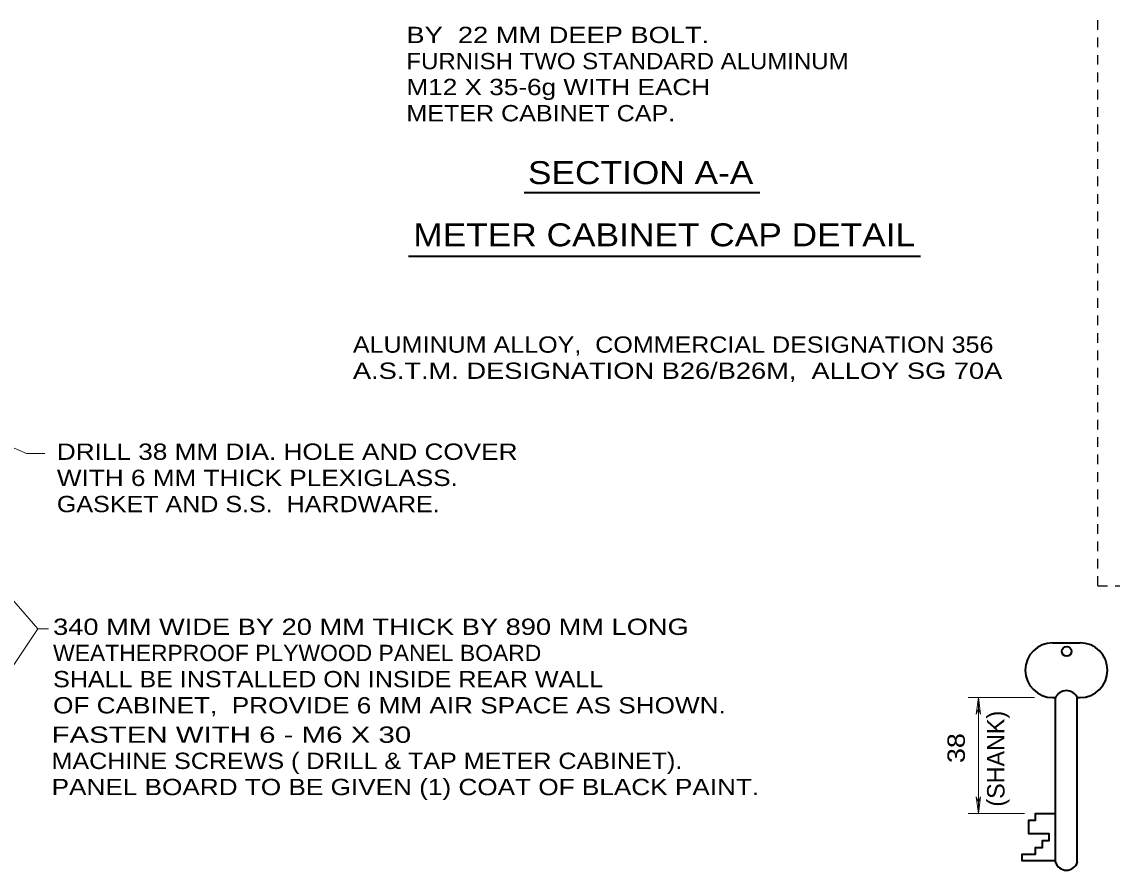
# Model space of a CAD drawing. Extents: x 312583 to 312853, y 144419 to 144586.
# Drawn here: x 312718.5 to 312769.3, y 144495.1 to 144534.6 of the extents above; entities that cross this region are included whole.
import ezdxf
from ezdxf.enums import TextEntityAlignment as Align

# ---------------------------------------------------------------- set-up
doc = ezdxf.new("R2010")
doc.units = 0
doc.header["$LTSCALE"] = 0.3
doc.linetypes.add('SHORT_DASHED', pattern=[2.7, 1.5, -1.2])
doc.layers.add('1', color=7, linetype='Continuous', lineweight=13)

msp = doc.modelspace()

# ---------------------------------------------------------------- linework, layer by layer
at = {"layer": '1', "linetype": 'SHORT_DASHED', "lineweight": 25}
for q in [(312768.638, 144560.0713), (312839.5547, 144508.3213)]:
    msp.add_line((312768.638, 144508.3213), q, dxfattribs=at)
at = {"layer": '1', "lineweight": 35}
for p, q in [((312741.8732, 144526.6628), (312752.8733, 144526.6628)), ((312736.4783, 144523.6918), (312760.3702, 144523.6918))]:
    msp.add_line(p, q, dxfattribs=at)
at = {"layer": '1'}
for p, q in [((312719.1969, 144506.3289), (312719.7029, 144506.3289)), ((312765.6863, 144503.1156), (312762.5813, 144503.1156)), ((312763.0643, 144503.1156), (312762.9647, 144502.3413)), ((312763.0643, 144497.7183), (312763.0643, 144503.1156)), ((312763.0643, 144503.1156), (312763.1563, 144502.3413)), ((312762.9647, 144502.3413), (312763.0643, 144502.5866)), ((312763.1563, 144502.3413), (312763.0643, 144502.5866)), ((312762.9647, 144498.4926), (312763.0643, 144498.2473)), ((312763.0643, 144497.7183), (312762.9647, 144498.4926)), ((312763.1563, 144498.4926), (312763.0643, 144498.2473)), ((312763.0643, 144497.7183), (312763.1563, 144498.4926)), ((312765.211, 144497.7183), (312762.5813, 144497.7183))]:
    msp.add_line(p, q, dxfattribs=at)
at = {"layer": '1', "lineweight": 40}
for p, q in [((312766.5297, 144505.6686), (312767.81, 144505.6686)), ((312766.5297, 144503.1156), (312766.66, 144503.1156)), ((312766.66, 144495.4489), (312766.66, 144503.1156)), ((312767.6797, 144495.4489), (312767.6797, 144503.1156)), ((312767.6797, 144503.1156), (312767.81, 144503.1156))]:
    msp.add_line(p, q, dxfattribs=at)
at = {"layer": '1'}
for points in [[(312713.5389, 144516.7095), (312718.6645, 144514.4903), (312719.5229, 144514.4903)], [(312715.3175, 144500.5329), (312719.1969, 144506.3289), (312715.1259, 144511.0055)]]:
    msp.add_lwpolyline(points, dxfattribs=at)
at = {"layer": '1', "lineweight": 40}
msp.add_lwpolyline([(312766.683, 144495.5026), (312765.1037, 144495.5026), (312765.1037, 144495.8169), (312765.7323, 144495.8169), (312765.7323, 144496.1313), (312766.0543, 144496.1313), (312766.0543, 144496.4533), (312766.3687, 144496.4533), (312766.3687, 144496.7676), (312765.418, 144496.7676), (312765.418, 144497.0819), (312765.418, 144497.4039), (312765.7323, 144497.4039), (312765.7323, 144497.7183), (312766.683, 144497.7183)], dxfattribs=at)
msp.add_circle((312767.1864, 144505.2674), 0.2251, dxfattribs=at)
for centre, radius, start, end in [((312766.5322, 144504.3934), 1.2778, 90, 180), ((312767.81, 144504.3934), 1.2778, 0, 90), ((312766.5322, 144504.3934), 1.2778, 180, 270), ((312767.81, 144504.3934), 1.2778, 270, 0), ((312767.1711, 144502.88), 0.5628, 24.74675, 155.25325), ((312767.1711, 144495.605), 0.5344, 196.98296, 343.01705)]:
    msp.add_arc(centre, radius, start, end, dxfattribs=at)

# ---------------------------------------------------------------- texts
at = {"layer": '1'}
for s, width, p in [('BY  22 MM DEEP BOLT.', 1.25, (312736.3895, 144533.6284)), ('FURNISH TWO STANDARD ALUMINUM', 1.1, (312736.3895, 144532.4084)), ('M12 X 35-6g WITH EACH', 1.2, (312736.3895, 144531.1996)), ('METER CABINET CAP.', 1.15, (312736.3895, 144529.9796)), ('ALUMINUM ALLOY,  COMMERCIAL DESIGNATION 356', 1.15, (312733.8935, 144519.1932)), ('A.S.T.M. DESIGNATION B26/B26M,  ALLOY SG 70A', 1.25, (312733.8935, 144517.9732)), ('DRILL 38 MM DIA. HOLE AND COVER', 1.2, (312720.0862, 144514.1997)), ('WITH 6 MM THICK PLEXIGLASS.', 1.2, (312720.0862, 144512.9797)), ('GASKET AND S.S.  HARDWARE.', 1.15, (312720.0862, 144511.7597)), ('340 MM WIDE BY 20 MM THICK BY 890 MM LONG', 1.25, (312719.9099, 144506.0365)), ('WEATHERPROOF PLYWOOD PANEL BOARD', 1.05, (312719.9099, 144504.8165)), ('SHALL BE INSTALLED ON INSIDE REAR WALL', 1.15, (312719.9099, 144503.5965)), ('OF CABINET,  PROVIDE 6 MM AIR SPACE AS SHOWN.', 1.2, (312719.9099, 144502.3765)), ('FASTEN WITH 6 - M6 X 30  ', 1.35, (312719.8398, 144501.0077)), ('MACHINE SCREWS ( DRILL & TAP METER CABINET).', 1.15, (312719.8398, 144499.7877)), ('PANEL BOARD TO BE GIVEN (1) COAT OF BLACK PAINT.', 1.2, (312719.8398, 144498.5677))]:
    msp.add_text(s, height=0.76, dxfattribs=dict(at, width=width)).set_placement(p)
at = {"layer": '1', "width": 1.15}
for s, p in [('SECTION A-A', (312747.3135, 144527.053)), ('METER CABINET CAP DETAIL', (312748.4129, 144524.1539))]:
    msp.add_text(s, height=1.07, dxfattribs=at).set_placement(p, align=Align.CENTER)
at = {"layer": '1'}
msp.add_text('(SHANK)', height=0.8126, rotation=90, dxfattribs=at).set_placement((312764.2833, 144500.2674), align=Align.CENTER)
at = {"layer": '1', "width": 1.15}
msp.add_text('38 ', height=0.8126, rotation=90, dxfattribs=at).set_placement((312762.4357, 144500.9341), align=Align.CENTER)

doc.saveas('drawing.dxf')
